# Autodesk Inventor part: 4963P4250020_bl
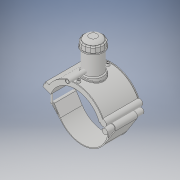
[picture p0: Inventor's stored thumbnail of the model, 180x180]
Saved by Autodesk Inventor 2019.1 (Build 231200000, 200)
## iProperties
Created: 2017-07
Part Number: 4963P4250020_bl
Material: Generic
Document SubType Name: Modeling
Designer: KIM
Density: 1 g/cm^3
Appearance: Default
Author: KIM
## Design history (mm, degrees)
derived "4963P4.ipt"
feature "Solid1::4963P4.ipt" dims "ScaleForDerivedMember" = 10
feature "Solid2::4963P4.ipt" dims "ScaleForDerivedMember" = 10
feature "Solid3::4963P4.ipt" dims "ScaleForDerivedMember" = 10
tag "TaggingFeature1"
body "Solid1"
body "Solid2"
body "Solid3"
other parameters: "d2" = 327.6 [user parameter], "d3" = 62.5 [user parameter], "d4" = 176 [user parameter], "d5" = 0 [user parameter], "d6" = 0.1 [user parameter], "d8" = 0 [user parameter], "d19" = 6 [user parameter], "d20" = 6 [user parameter], "d21" = 105.6 [user parameter], "d23" = 0 [user parameter], "d24" = 52.8 [user parameter], "d26" = 0 [user parameter], "d27" = 3 [user parameter], "d28" = 3 [user parameter], "d29" = 3 [user parameter], "d30" = 83.33333 [user parameter], "d31" = 6 [user parameter], "d32" = 0 [user parameter], "d33" = 0 [user parameter], "d34" = 0.6 [user parameter], "d40" = 150.8 [user parameter], "d43" = 0 [user parameter], "d45" = 0 [user parameter], "d47" = 250.6 [user parameter], "d70" = 15 [user parameter], "d72" = 0 [user parameter], "d73" = 6 [user parameter], "d75" = 5 [user parameter], "d76" = 0 [user parameter], "d77" = 12.5 [user parameter], "d78" = 155 [user parameter], "d79" = 15 [user parameter], "d80" = 70.4 [user parameter], "d82" = 5 deg [user parameter], "d84" = 4 [user parameter], "d85" = 14 [user parameter], "d86" = 0 [user parameter], "d87" = 3 [user parameter], "d88" = 0 [user parameter], "d89" = 1 [user parameter], "d90" = 1 [user parameter], "d91" = 140.8 [user parameter], "d92" = 0 [user parameter], "d93" = 0.5 [user parameter], "d94" = 131.57895 [user parameter], "d96" = 295.8 [user parameter], "d97" = 3.52 [user parameter], "d98" = 0 [user parameter], "d102" = 2.5 [user parameter], "d120" = 140 deg [user parameter], "d121" = 24.228 [user parameter], "d122" = 20 deg [user parameter], "d124" = 174 [user parameter], "d126" = 0 [user parameter], "d143" = 257.5 [user parameter], "d145" = 30.76923 [user parameter], "d149" = 3.75 [user parameter], "d150" = 33.84615 [user parameter], "d153" = 176 [user parameter], "d154" = 0 [user parameter], "d156" = 145 [user parameter], "d157" = 160 deg [user parameter], "d159" = 8 [user parameter], "d161" = 3.75 [user parameter], "d162" = 105.6 [user parameter], "d163" = 0 [user parameter], "d164" = 125 [user parameter], "d167" = 25 [user parameter], "d168" = 141.46341 [user parameter], "d170" = 3.75 [user parameter], "d172" = 0 [user parameter], "d173" = 1 [user parameter], "d175" = 125 [user parameter], "d176" = 20 deg [user parameter], "d177" = 17.5 [user parameter], "d180" = 0 [user parameter], "d183" = 16 [user parameter], "d184" = 14 [user parameter], "d185" = 57.2 [user parameter], "d186" = 57.2 [user parameter], "d187" = 145 [user parameter], "d188" = 12 [user parameter], "d189" = 17.5 [user parameter], "d190" = 0 [user parameter], "d191" = 217.5 [user parameter], "d193" = 8 [user parameter], "d194" = 6.16 [user parameter], "d195" = 90 deg [user parameter], "d197" = 0 [user parameter], "d199" = 0 [user parameter], "d202" = 0 [user parameter], "d203" = 177 [user parameter], "d204" = 95 [user parameter], "d206" = 85 [user parameter], "d207" = 132.75 [user parameter], "d208" = 138.06 [user parameter], "d209" = 164.61 [user parameter], "d210" = 86 [user parameter], "d213" = 36 [user parameter], "d216" = 0 [user parameter], "d217" = 25 [user parameter], "d218" = 25 [user parameter], "d219" = 5 [user parameter], "d224" = 0 [user parameter], "d227" = 16 [user parameter], "d228" = 125 [user parameter], "d230" = 5 [user parameter], "B_" = 252 [user parameter], "L_" = 176 [user parameter], "d_t" = 6 [user parameter], "H_2" = 177 [user parameter], "H_" = 125 [user parameter], "d148" = 3.75 [user parameter], "d160" = 3.75 [user parameter], "d169" = 3.75 [user parameter], "d192" = 8 [user parameter]
